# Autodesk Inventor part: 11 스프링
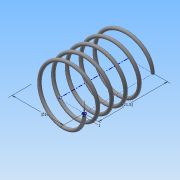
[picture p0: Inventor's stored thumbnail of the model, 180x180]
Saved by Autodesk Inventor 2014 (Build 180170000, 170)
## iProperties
Created: 2015-06
Part Number: 11 스프링
Material: 강철, 연강
Document SubType Name: Modeling
Designer: Administrator
Density: 7.86 g/cm^3
Appearance: 강철
Mass: 1.53535 g
Surface Area: 7.89042 cm^2
Volume: 0.195337 cm^3
Author: Administrator
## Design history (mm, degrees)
sketch "스케치1"
  geometry: L1 (0, 0)-(8, 0); L2 (8, 0)-(8, 21.5); L3 (8, 21.5)-(0, 21.5); L4 (0, 21.5)-(0, 0); C1 r 0.5 at (8, 0)
  constraints: 8 end point, 2 parallel, 1 centre point, 1 coincident, 1 horizontal, 1 perpendicular
  dimensions: "d0" = 16 diameter of L2 L4; "d1" = 21.5 distance of L1.end L2.end (derived); "d2" = 1 diameter of C1
feature "코일1" sketch "스케치1" pitch "d3" = 10; turns "d5" = 5; dims "d4" = 21.5 (= d1), "d6" = 0, angle "d7" = 90 deg, angle "d8" = 90 deg, "d9" = 0, "d10" = 0
sketch "스케치2"
  geometry: L1 (-8.5, 0)-(-7.5, 0) reference; 1 further point
  constraints: 1 horizontal alignment
extrude "돌출1" cut sketch "스케치2" stored distance "d11" = 10; taper "d12" = 0 deg
node "작업 평면1"
sketch "스케치3"
  geometry: L1 (8.5, 0)-(7.5, 0) reference; 1 further point
  constraints: 1 horizontal alignment
extrude "돌출2" cut sketch "스케치3" stored distance "d14" = 10; taper "d15" = 0 deg
node "솔리드1"
node "절단 모서리 투영1"
node "절단 모서리 투영2"
other parameters: "d13" = -21.5 (= -d1)
